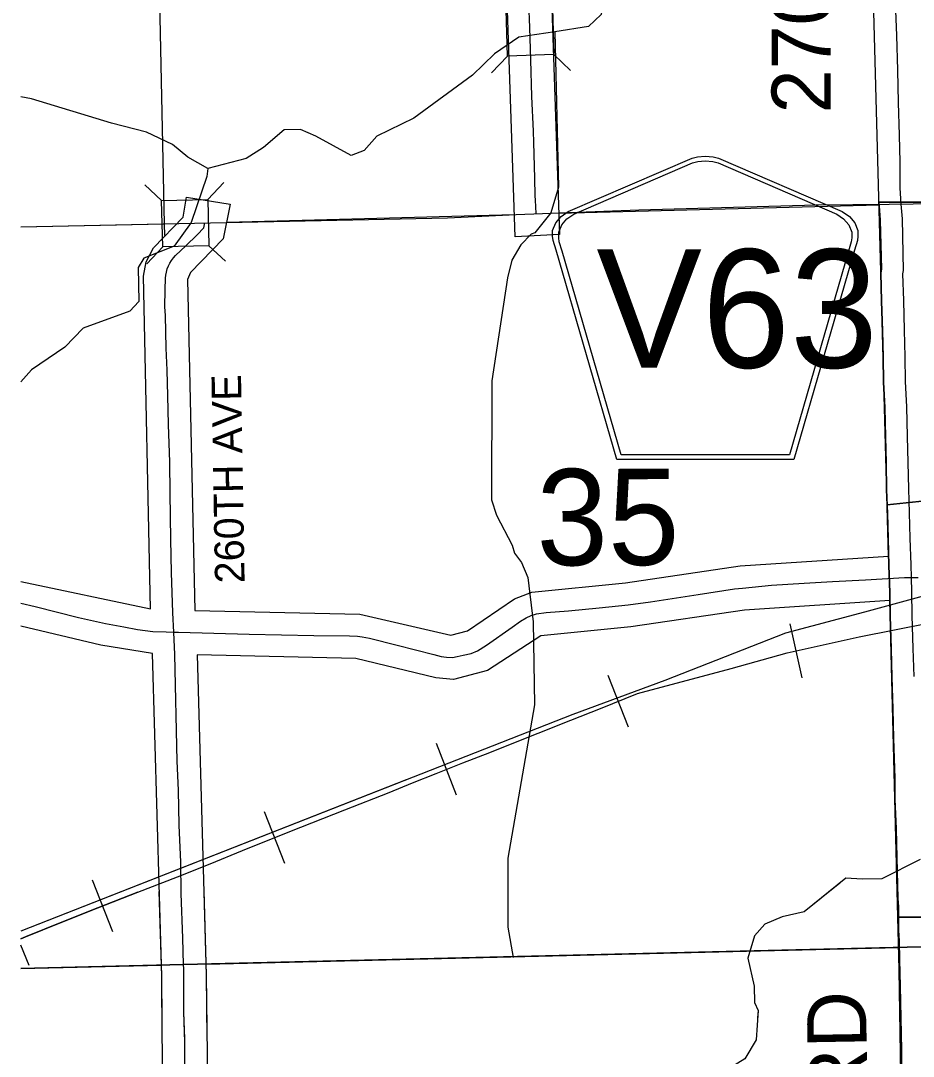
# Model space of a CAD drawing. Extents: x 10133 to 81668, y 7924 to 11018.
# Drawn here: x 10954.9 to 11135.9, y 9007.3 to 9217.2 of the extents above; entities that cross this region are included whole.
import ezdxf

# ---------------------------------------------------------------- set-up
doc = ezdxf.new("R2010")
doc.units = 0
for name, color, linetype in [('tdCoCityStreetMajor', 7, 'Continuous'), ('tdCoCityStreetMinor', 7, 'Continuous'), ('tdCoHydroRiver', 7, 'Continuous'), ('tdCoPriNonDiv', 7, 'Continuous'), ('tdCoRRCL', 7, 'Continuous'), ('tdCoRROwnerTxt', 7, 'Continuous'), ('tdCoSecRteBand', 7, 'Continuous'), ('tdCoShieldCoRte', 7, 'Continuous'), ('tdCoShieldCoRteHrd', 7, 'Continuous'), ('tdCoShieldStRte', 7, 'Continuous'), ('tdCoStrucNonDivPri', 7, 'Continuous'), ('tdCoStrucSec', 7, 'Continuous'), ('tdCoSurfAsphalt', 7, 'Continuous'), ('tdCoTwpNameTxt', 7, 'Continuous'), ('tdCoTwpRngTxt', 7, 'Continuous'), ('tdCoUnicrpTwnTxt', 7, 'Continuous')]:
    doc.layers.add(name, color=color, linetype=linetype)

msp = doc.modelspace()

# ---------------------------------------------------------------- linework, layer by layer
at = {"layer": 'tdCoCityStreetMajor'}
for points in [[(11133.39, 9180.01), (11133.3, 9181.12), (11133.2, 9183.22), (11133.18, 9188.5), (11133.05, 9193.97), (11132.86, 9200.61), (11132.71, 9207.14), (11132.51, 9214.19), (11132.34, 9219.25)], [(10988.13, 9010.77), (10987.95, 9016.17), (10987.98, 9023.55), (10987.93, 9024.98), (10987.91, 9025.85), (10987.73, 9031.17), (10987.44, 9040.27), (10987.36, 9046.58), (10987.04, 9054.1), (10986.87, 9061.2), (10986.6, 9067.07), (10986.13, 9088.68), (10985.9, 9093.25)], [(10988.47, 8962.63), (10988.42, 8976.17), (10988.45, 8984.34), (10988.19, 8999.21), (10988.16, 9010.09), (10987.95, 9016.17), (10987.98, 9023.55), (10987.93, 9024.98), (10987.91, 9025.85), (10987.73, 9031.17), (10987.44, 9040.27), (10987.43, 9040.75)]]:
    msp.add_lwpolyline(points, dxfattribs=at)
at = {"layer": 'tdCoCityStreetMinor'}
for points in [[(10985.9, 9093.25), (10985.71, 9097.16), (10985.44, 9105.3), (10985.32, 9112.05), (10985.17, 9121.38), (10985.09, 9127.69), (10984.87, 9135.36), (10984.7, 9141.15), (10984.6, 9146.36), (10984.4, 9150.8), (10984.23, 9157.43), (10984.13, 9159.16), (10984.2, 9162.61), (10984.23, 9164.98), (10984.29, 9165.62), (10984.41, 9166.25), (10984.59, 9166.87), (10984.82, 9167.47), (10985.12, 9168.04), (10985.46, 9168.59), (10985.86, 9169.1), (10986.3, 9169.57), (10988.34, 9171.54), (10990.64, 9173.81), (10992.02, 9175.19), (10992.19, 9176.25)], [(10985.9, 9093.25), (10986.87, 9093.23), (11001.2, 9092.86), (11014.32, 9092.54), (11021.55, 9092.46), (11023.17, 9092.42), (11024.09, 9092.32), (11025.57, 9092), (11031.24, 9090.59), (11038.68, 9088.69), (11040.16, 9088.32), (11041.2, 9088.15), (11042.43, 9088.12), (11043.4, 9088.3), (11044.58, 9088.57), (11046.23, 9088.94), (11047.51, 9089.46), (11049.31, 9090.57), (11054.54, 9094.22), (11056.24, 9095.45), (11057.38, 9096.16), (11058.36, 9096.63), (11059.45, 9096.93), (11061.42, 9097.2), (11065.93, 9097.54), (11072.17, 9098.16), (11078.02, 9098.78), (11082.58, 9099.37), (11092.25, 9100.9), (11099.6, 9102.01), (11101.2, 9102.18), (11107.09, 9102.75), (11113.75, 9103.19), (11119.5, 9103.51), (11126.18, 9103.86), (11134.07, 9104.33), (11135.49, 9104.34), (11136.86, 9104.35)], [(10954.88, 9099.1), (10957.82, 9098.41), (10966.6, 9096.19), (10972.1, 9094.98), (10975.8, 9094.31), (10978.56, 9093.77), (10981.69, 9093.4), (10984.38, 9093.28), (10985.9, 9093.25)]]:
    msp.add_lwpolyline(points, dxfattribs=at)
at = {"layer": 'tdCoHydroRiver'}
for points in [[(11087.94, 9234.8), (11086.82, 9230.75), (11085.44, 9228.36), (11082.65, 9225.24), (11079.83, 9223.77), (11073.94, 9222.25), (11073.01, 9221.29), (11072.58, 9218.44), (11070.02, 9216.03), (11063.17, 9214.96)], [(11063.17, 9214.96), (11055.85, 9213.89), (11050.93, 9210.5), (11046.51, 9206.16), (11034.58, 9197.44), (11027.06, 9193.76), (11024.5, 9190.87), (11021.91, 9189.88), (11014.75, 9193.79), (11011.64, 9195.16), (11008.33, 9195.1), (11004.13, 9191.48), (11000.61, 9189.29), (10992.83, 9187.26)], [(11063.17, 9214.96), (11063.93, 9183.48), (11062.36, 9178.25), (11059.12, 9174.17), (11058.41, 9173.92), (11056.32, 9171.75), (11054.48, 9168.64), (11053.59, 9165.08), (11050.39, 9144.18), (11050.32, 9120.03), (11051.32, 9116.97), (11054.5, 9110.87), (11055, 9109.22), (11056.45, 9107.35), (11057.69, 9104.29), (11058.78, 9095.31), (11059.07, 9078.5), (11053.67, 9047.39), (11053.67, 9033.42), (11054.72, 9027.28)], [(10992.83, 9187.26), (10988.77, 9189.56), (10985.65, 9192.12), (10980.4, 9194.63), (10973.26, 9196.41), (10957.08, 9201.34), (10954.88, 9201.77)], [(10992.83, 9187.26), (10992.62, 9185.6), (10989.47, 9176.31), (10985.99, 9171.52), (10979.88, 9169.05), (10978.73, 9167.13), (10978.84, 9160.27), (10976.98, 9158.34), (10967.57, 9154.87), (10963.84, 9151.02), (10957.05, 9146.41), (10954.88, 9144)], [(11137.26, 9047.13), (11129.51, 9043.22), (11125.49, 9043.15), (11122.17, 9043.33), (11113.76, 9036.56), (11109.28, 9035.54), (11105.75, 9034.05), (11103.66, 9031.65), (11102.31, 9027.13), (11103.59, 9021.47), (11103.65, 9018.15), (11104.39, 9016.51), (11104.29, 9015.02)], [(11120.97, 9042.37), (11113.75, 9036.56), (11109.27, 9035.53), (11105.74, 9034.05), (11103.65, 9031.65), (11102.31, 9027.13), (11103.59, 9021.47), (11103.64, 9018.15), (11104.38, 9016.51), (11104.01, 9010.58), (11101.7, 9006.76), (11096.55, 9003.59), (11091.16, 8999.95), (11087.17, 8998.22), (11075.79, 8998.74), (11071.08, 8997.24), (11056.36, 8985.63), (11050.78, 8979.14), (11047.08, 8974.11), (11040.8, 8967.37)]]:
    msp.add_lwpolyline(points, dxfattribs=at)
at = {"layer": 'tdCoPriNonDiv'}
for points in [[(10954.88, 9329.4), (11026.96, 9330.97), (11055.14, 9332.08), (11057.01, 9331.75), (11058.57, 9330.68), (11059.81, 9327.57), (11060.13, 9291.52), (11064.1, 9173.84), (11055.11, 9173.41), (11051.14, 9291.25), (11050.79, 9322.9), (10954.88, 9320.53)], [(10954.88, 9103.53), (10981.18, 9097.99), (10979.75, 9165.4), (10980.33, 9168.33), (10981.78, 9171.18), (10987.81, 9177.34), (10988.47, 9181.41), (10997.35, 9179.97), (10995.93, 9172.96), (10989.28, 9166.17), (10988.72, 9164.75), (10990.2, 9097.64), (11023.66, 9096.89), (11042.08, 9092.63), (11045.48, 9093.48), (11054.98, 9099.97), (11058.55, 9101.34), (11077.49, 9103.25), (11100.77, 9106.66), (11130.85, 9108.64), (11127.4, 9236.64)], [(11133.29, 9014.12), (11131.11, 9099.64), (11101.66, 9097.71), (11078.6, 9094.32), (11060.35, 9092.51), (11049.54, 9085.44), (11042.64, 9083.63), (11039.07, 9083.96), (11022.86, 9087.92), (10990.63, 9088.63), (10992.48, 9023.69), (10992.64, 9010.87)], [(10983.58, 9010.66), (10983.48, 9023.48), (10981.61, 9088.9), (10971.14, 9090.59), (10954.88, 9094.46)], [(10994.21, 8884.49), (11135.19, 8887.56), (11133.43, 9008.58), (11132.53, 9044.1)], [(10954.88, 8958.83), (10983.99, 8959.51), (10983.48, 9023.48), (10982.99, 9040.65)], [(10991.99, 9040.85), (10992.48, 9023.69), (10994.21, 8884.49)]]:
    msp.add_lwpolyline(points, dxfattribs=at)
at = {"layer": 'tdCoRRCL'}
for p, q in [((11113.36, 9083.96), (11110.9, 9094.94)), ((11078.15, 9073.99), (11074.01, 9084.46)), ((11043.25, 9060.17), (11039.18, 9070.66)), ((11033.05, 9063.29), (10954.88, 9032.6)), ((11008.45, 9046.33), (11004.29, 9056.78)), ((10973.54, 9032.5), (10969.47, 9042.99)), ((10956.57, 9025.67), (10954.88, 9029.79))]:
    msp.add_line(p, q, dxfattribs=at)
for points in [[(11383.11, 9177.72), (11374.43, 9174.35), (11360.55, 9167.76), (11338.88, 9160.33), (11251.25, 9129.22), (11226.5, 9121.28), (11195.58, 9114.67), (11163.03, 9105.91), (11145.32, 9102.57), (11125.98, 9097.32), (11109.94, 9093.06), (11085.46, 9083.46), (11066.85, 9076.56), (10954.88, 9032.59)], [(10954.88, 9031.05), (10955.87, 9031.46), (10963.19, 9034.41), (10970.5, 9037.35), (10978.6, 9040.5), (10986.7, 9043.65), (10993.27, 9046.3), (10999.83, 9048.95), (11005.75, 9051.31), (11011.67, 9053.67), (11020.61, 9057.21), (11029.56, 9060.75), (11034.34, 9062.68), (11039.11, 9064.6), (11044.54, 9066.71), (11049.97, 9068.81), (11054.88, 9070.78), (11059.8, 9072.74), (11066.45, 9075.4), (11072.42, 9077.78), (11079.97, 9080.77), (11098.96, 9085.86), (11110.29, 9089.04), (11124.89, 9092.32), (11146.01, 9096.47)], [(10978.6, 9040.5), (10970.5, 9037.36), (10963.19, 9034.41), (10955.87, 9031.46), (10954.88, 9031.05)], [(10954.88, 9031.05), (10955.87, 9031.46), (10963.19, 9034.41), (10970.5, 9037.36), (10978.6, 9040.5)]]:
    msp.add_lwpolyline(points, dxfattribs=at)
at = {"layer": 'tdCoSecRteBand'}
for points in [[(11059.39, 9178.12), (11059.26, 9180.83), (11059.22, 9181.72), (11059.11, 9185.29), (11058.9, 9192.5), (11058.87, 9194.83), (11058.54, 9201.86), (11058.3, 9209.23), (11058.1, 9215.84), (11057.9, 9220.82)], [(11136.01, 9084.23), (11135.84, 9089.95), (11135.64, 9096.61), (11135.59, 9101.4), (11135.49, 9104.34), (11135.4, 9106.9), (11135.25, 9112.32), (11135.08, 9117.43), (11134.93, 9122.28), (11134.83, 9127.64), (11134.71, 9132.91), (11134.53, 9138.93), (11134.31, 9144.08), (11134.21, 9149.07), (11134.07, 9154.44), (11133.92, 9160.46), (11133.77, 9165.86), (11133.87, 9166.58), (11133.64, 9177.01), (11133.39, 9180.01)]]:
    msp.add_lwpolyline(points, dxfattribs=at)
at = {"layer": 'tdCoShieldCoRte'}
for points in [[(11065.84, 9223.04), (11062.69, 9219.7), (11062.96, 9210.32)], [(11050.36, 9206.63), (11053.58, 9210.04), (11053.31, 9219.42)], [(11066.38, 9207.1), (11062.96, 9210.32), (11053.58, 9210.04)]]:
    msp.add_lwpolyline(points, dxfattribs=at)
at = {"layer": 'tdCoShieldCoRteHrd'}
for q in [(10983.42, 9025.74), (10983.43, 9025.74)]:
    msp.add_line((10954.88, 9025.06), q, dxfattribs=at)
for points in [[(10992.42, 9025.95), (11133.01, 9029.32)], [(10992.42, 9025.96), (11133.02, 9029.32)]]:
    msp.add_lwpolyline(points, dxfattribs=at)
at = {"layer": 'tdCoStrucNonDivPri'}
for p, q in [((10954.88, 9175.42), (10983.99, 9176.04)), ((10954.88, 9025.06), (10983.42, 9025.74)), ((10954.88, 9025.06), (10983.43, 9025.74))]:
    msp.add_line(p, q, dxfattribs=at)
for points in [[(10980.9, 9320.97), (10983.99, 9176.04)], [(11063.96, 9178.16), (11128.9, 9179.89)], [(10996.77, 9176.38), (11054.96, 9177.93)], [(10983.99, 9176.04), (10986.56, 9176.11)], [(10983.99, 9176.04), (10984.06, 9173.66)], [(10992.42, 9025.95), (11133.01, 9029.32)], [(10992.42, 9025.96), (11133.02, 9029.32)]]:
    msp.add_lwpolyline(points, dxfattribs=at)
at = {"layer": 'tdCoStrucSec'}
msp.add_lwpolyline([(10954.88, 9175.44), (11041.44, 9177.24), (11055.35, 9177.93), (11080.24, 9178.84), (11116.14, 9179.9), (11130.94, 9179.97), (11160.16, 9180.44), (11189.9, 9180.57), (11314.49, 9181.85), (11344.65, 9183.03), (11380.85, 9184.91), (11405.4, 9186.53), (11423.46, 9187.1), (11448.12, 9188.29), (11485.13, 9189.73)], dxfattribs=at)
at = {"layer": 'tdCoSurfAsphalt'}
for p, q in [((11137.88, 9180.38), (11128.88, 9180.38)), ((11128.88, 9180.38), (11128.91, 9179.63)), ((11137.9, 9180.39), (11128.9, 9180.39)), ((11128.9, 9180.39), (11128.93, 9179.64))]:
    msp.add_line(p, q, dxfattribs=at)
for points in [[(11139.52, 9119.99), (11130.55, 9119.04), (11130.45, 9122.19), (11130.35, 9127.55), (11130.23, 9132.81), (11130.06, 9138.78), (11129.84, 9143.95), (11129.74, 9148.97), (11129.59, 9154.34), (11129.44, 9160.35), (11129.28, 9166.11), (11129.38, 9166.85), (11129.17, 9176.79), (11128.93, 9179.64), (11128.9, 9180.39), (11137.9, 9180.39)], [(11128.91, 9179.63), (11129.15, 9176.78), (11129.36, 9166.84), (11129.26, 9166.1), (11129.42, 9160.34), (11129.57, 9154.32), (11129.71, 9148.96), (11129.81, 9143.94), (11130.04, 9138.77), (11130.21, 9132.8), (11130.33, 9127.54), (11130.43, 9122.17), (11130.58, 9117.28), (11130.75, 9112.18), (11130.9, 9106.75), (11131.09, 9101.29), (11131.14, 9096.52), (11131.34, 9089.82), (11131.52, 9084.1), (11131.69, 9077.68), (11131.84, 9071.65), (11132.08, 9063.63), (11132.11, 9059.34), (11132.35, 9053.38), (11132.5, 9047.52), (11132.73, 9039.2), (11132.85, 9037.57), (11132.87, 9032.75), (11132.95, 9030.65), (11133.04, 9026.84), (11133.17, 9021.47), (11133.32, 9014.14)], [(11128.93, 9179.64), (11129.17, 9176.79), (11129.38, 9166.85), (11129.28, 9166.11), (11129.44, 9160.35), (11129.59, 9154.34), (11129.74, 9148.97), (11129.84, 9143.95), (11130.06, 9138.78), (11130.23, 9132.81), (11130.35, 9127.55), (11130.45, 9122.19), (11130.6, 9117.29), (11130.77, 9112.2), (11130.92, 9106.77), (11131.12, 9101.3), (11131.17, 9096.53), (11131.37, 9089.83), (11131.54, 9084.12), (11131.71, 9077.69), (11131.86, 9071.67), (11132.1, 9063.65), (11132.13, 9059.35), (11132.38, 9053.39), (11132.53, 9047.53), (11132.75, 9039.21), (11132.87, 9037.58), (11132.89, 9032.76), (11132.97, 9030.67), (11133.07, 9026.85), (11133.19, 9021.48), (11133.34, 9014.15)], [(11141.88, 9035.44), (11132.88, 9035.44), (11132.87, 9037.58), (11132.75, 9039.21), (11132.62, 9044.1), (11132.53, 9047.53), (11132.38, 9053.39), (11132.13, 9059.35), (11132.1, 9063.65), (11131.86, 9071.67), (11131.71, 9077.69), (11131.54, 9084.12), (11131.37, 9089.83), (11131.17, 9096.53), (11131.12, 9101.3), (11130.92, 9106.77), (11130.77, 9112.2), (11130.6, 9117.29), (11130.55, 9119.04), (11139.52, 9119.99)], [(11132.59, 9044.09), (11132.73, 9039.2), (11132.85, 9037.57), (11132.87, 9032.75), (11132.95, 9030.66), (11133.04, 9026.84), (11133.17, 9021.47), (11133.43, 9008.58), (11133.5, 8999.89), (11133.8, 8982.53), (11133.95, 8972.33), (11134.13, 8957.66), (11134.35, 8947.54), (11134.5, 8929.9), (11134.91, 8905.21), (11135.17, 8888.98), (11135.3, 8879.22)], [(11132.62, 9044.1), (11132.75, 9039.21), (11132.87, 9037.58), (11132.89, 9032.76), (11132.97, 9030.67), (11133.07, 9026.85), (11133.19, 9021.49), (11133.45, 9008.59), (11133.53, 8999.9), (11133.82, 8982.54), (11133.97, 8972.34), (11134.15, 8957.68), (11134.38, 8947.55), (11134.52, 8929.92), (11134.93, 8905.23), (11135.19, 8888.99), (11135.32, 8879.23)]]:
    msp.add_lwpolyline(points, dxfattribs=at)
msp.add_lwpolyline([(11132.89, 9033.19), (11132.88, 9035.44), (11141.88, 9035.44), (11146.71, 8738.97), (11294.17, 8746), (11308.79, 8746.04), (11334.35, 8746.15), (11366.91, 8746.3), (11391.58, 8746.26), (11425.21, 8746.56), (11449.9, 8746.78), (11483.73, 8746.82), (11483.73, 8737.82), (11483.67, 8737.82), (11449.95, 8737.78), (11425.29, 8737.56), (11391.61, 8737.26), (11366.93, 8737.3), (11334.39, 8737.15), (11308.82, 8737.04), (11294.37, 8737), (11219.06, 8732.98), (11137.76, 8729.58)], close=True, dxfattribs=at)
at = {"layer": 'tdCoTwpNameTxt'}
for points in [[(12204.65, 9594.91), (12205.81, 9506.76), (12207.26, 9355.85), (12207.65, 9199.23), (12206.71, 9053.29), (12058.44, 9052.45), (12055.44, 9052.43), (11906.7, 9050.03), (11903.62, 9049.96), (11751.72, 9046.27), (11602.3, 9041.92), (11599.58, 9041.89), (11448.66, 9038.75), (11287.47, 9032.68), (11137.48, 9029.42), (10987.91, 9025.85), (10954.88, 9025.06)], [(10954.88, 9025.06), (10987.91, 9025.85), (11137.48, 9029.42), (11287.46, 9032.68), (11448.65, 9038.75), (11599.58, 9041.89), (11602.29, 9041.92), (11751.71, 9046.27), (11903.62, 9049.96), (11906.69, 9050.03), (12055.44, 9052.43), (12058.43, 9052.45), (12206.7, 9053.29), (12354.1, 9050.96), (12408.9, 9050.4)]]:
    msp.add_lwpolyline(points, dxfattribs=at)
at = {"layer": 'tdCoTwpRngTxt'}
for points in [[(10980.03, 9183.95), (10983.44, 9180.72), (10992.82, 9180.96)], [(10996.05, 9184.37), (10992.82, 9180.96), (10993.06, 9171.58)], [(10980.44, 9167.94), (10983.68, 9171.34), (10983.44, 9180.72)], [(10996.39, 9168.42), (10993.06, 9171.58), (10983.68, 9171.34)]]:
    msp.add_lwpolyline(points, dxfattribs=at)
at = {"layer": 'tdCoUnicrpTwnTxt'}
for points in [[(11075.72, 9128.21), (11063.43, 9170.65), (11062.85, 9172.62), (11062.74, 9173.5), (11062.74, 9174.68), (11063.38, 9176.22), (11064.47, 9177.49), (11065.9, 9178.5), (11091, 9189.35), (11092.12, 9189.59), (11093.69, 9189.73), (11095.25, 9189.59), (11096.38, 9189.35), (11121.47, 9178.5), (11122.91, 9177.49), (11124, 9176.22), (11124.63, 9174.68), (11124.63, 9173.5), (11124.52, 9172.62), (11123.94, 9170.65), (11111.65, 9128.21)], [(11076.6, 9129.16), (11064.64, 9170.45), (11064.08, 9172.35), (11063.98, 9173.19), (11063.98, 9174.32), (11064.59, 9175.8), (11065.64, 9177.03), (11067.02, 9177.99), (11091.1, 9188.41), (11092.19, 9188.64), (11093.69, 9188.77), (11095.19, 9188.64), (11096.27, 9188.41), (11120.36, 9177.99), (11121.74, 9177.03), (11122.78, 9175.8), (11123.39, 9174.32), (11123.39, 9173.19), (11123.29, 9172.35), (11122.73, 9170.45), (11110.77, 9129.16)]]:
    msp.add_lwpolyline(points, close=True, dxfattribs=at)

# ---------------------------------------------------------------- texts
at = {"layer": 'tdCoRROwnerTxt'}
msp.add_text('35', height=19.5, rotation=0.2259, dxfattribs=at).set_placement((11059.48, 9106.78))
at = {"layer": 'tdCoShieldStRte'}
for s, height, rotation, p in [('270TH AVE', 12, 90, (11119.14, 9198.39)), ('260TH AVE', 6, 91, (11000.29, 9103.18)), ('PACKWOOD RD', 12, 91, (11128.37, 8897.55))]:
    msp.add_text(s, height=height, rotation=rotation, dxfattribs=at).set_placement(p)
at = {"layer": 'tdCoUnicrpTwnTxt'}
msp.add_text('V63', height=24, dxfattribs=at).set_placement((11071.6, 9146.85))

doc.saveas('drawing.dxf')
